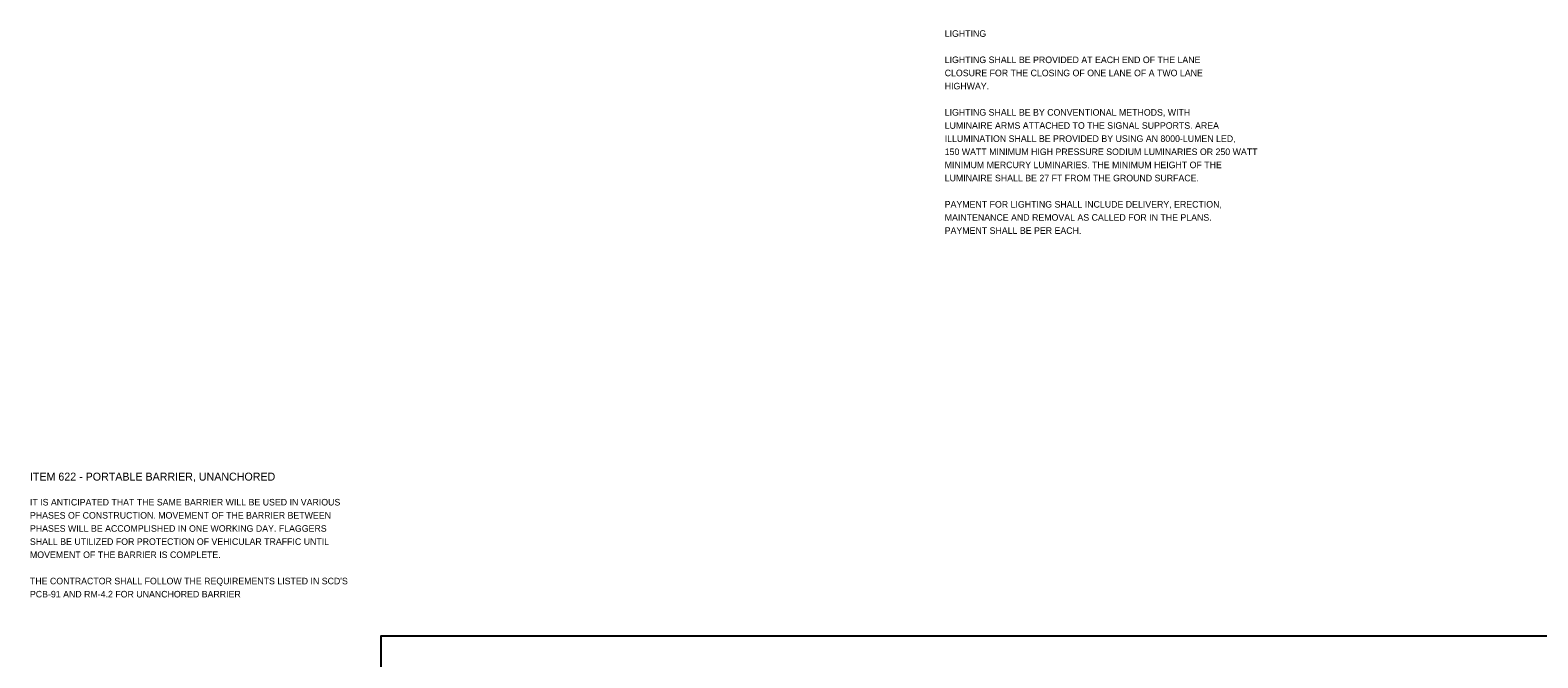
# Model space of a CAD drawing. Extents: x -7.5 to 46.3, y -5.1 to 34.9.
# Drawn here: x -7.48 to 24.66, y 21.54 to 34.92 of the extents above; entities that cross this region are included whole.
import ezdxf

# ---------------------------------------------------------------- set-up
doc = ezdxf.new("R2010")
doc.units = 0
doc.layers.add('SH_Cut_Line', color=7, linetype='Continuous')
doc.layers.add('SH_Text', color=7, linetype='Continuous')

msp = doc.modelspace()

# ---------------------------------------------------------------- linework, layer by layer
at = {"layer": 'SH_Cut_Line'}
msp.add_lwpolyline([(0, 0), (34, 0), (34, 22), (0, 22)], close=True, dxfattribs=at)

# ---------------------------------------------------------------- texts
at = {"layer": 'SH_Text'}
for s, height, p in [('LIGHTING', 0.14, (12.017, 34.773)), ('CLOSURE FOR THE CLOSING OF ONE LANE OF A TWO LANE', 0.14, (12.017, 33.933)), ('LIGHTING SHALL BE PROVIDED AT EACH END OF THE LANE', 0.14, (12.017, 34.213)), ('HIGHWAY.', 0.14, (12.017, 33.653)), ('LIGHTING SHALL BE BY CONVENTIONAL METHODS, WITH', 0.14, (12.017, 33.093)), ('LUMINAIRE ARMS ATTACHED TO THE SIGNAL SUPPORTS. AREA', 0.14, (12.017, 32.813)), ('ILLUMINATION SHALL BE PROVIDED BY USING AN 8000-LUMEN LED,', 0.14, (12.017, 32.533)), ('150 WATT MINIMUM HIGH PRESSURE SODIUM LUMINARIES OR 250 WATT', 0.14, (12.017, 32.253)), ('MINIMUM MERCURY LUMINARIES. THE MINIMUM HEIGHT OF THE', 0.14, (12.017, 31.973)), ('LUMINAIRE SHALL BE 27 FT FROM THE GROUND SURFACE.', 0.14, (12.017, 31.693)), ('PAYMENT FOR LIGHTING SHALL INCLUDE DELIVERY, ERECTION,', 0.14, (12.017, 31.133)), ('MAINTENANCE AND REMOVAL AS CALLED FOR IN THE PLANS.', 0.14, (12.017, 30.853)), ('PAYMENT SHALL BE PER EACH.', 0.14, (12.017, 30.573)), ('ITEM 622 - PORTABLE BARRIER, UNANCHORED', 0.17, (-7.482, 25.314)), ('IT IS ANTICIPATED THAT THE SAME BARRIER WILL BE USED IN VARIOUS ', 0.14, (-7.482, 24.784)), ('PHASES OF CONSTRUCTION. MOVEMENT OF THE BARRIER BETWEEN ', 0.14, (-7.482, 24.504)), ('PHASES WILL BE ACCOMPLISHED IN ONE WORKING DAY. FLAGGERS ', 0.14, (-7.482, 24.224)), ('SHALL BE UTILIZED FOR PROTECTION OF VEHICULAR TRAFFIC UNTIL ', 0.14, (-7.482, 23.944)), ('MOVEMENT OF THE BARRIER IS COMPLETE.', 0.14, (-7.482, 23.664)), ("THE CONTRACTOR SHALL FOLLOW THE REQUIREMENTS LISTED IN SCD'S ", 0.14, (-7.482, 23.104)), ('PCB-91 AND RM-4.2 FOR UNANCHORED BARRIER', 0.14, (-7.482, 22.824))]:
    msp.add_text(s, height=height, dxfattribs=at).set_placement(p)

doc.saveas('drawing.dxf')
